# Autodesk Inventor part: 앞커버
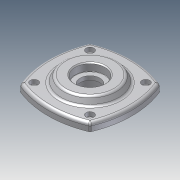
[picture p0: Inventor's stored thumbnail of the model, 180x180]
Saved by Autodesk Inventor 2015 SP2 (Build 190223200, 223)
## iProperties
Created: 2013-02
Part Number: 앞커버
Document SubType Name: Modeling
Designer: 한국산업디자인학원[gmhk.co.kr]
Density: 1 g/cm^3
Material: 일반
Appearance: 기본값
Mass: 76.2425 g
Surface Area: 198.108 cm^2
Volume: 76.2425 cm^3
Author: 한국산업디자인학원[gmhk.co.kr]
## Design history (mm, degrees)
sketch "스케치1"
  geometry: C1 r 30 at (0, 0) reference; A1 r 91.05 centre (0, -48.55) between (34.185, 35.839) and (-34.185, 35.839) reference; A2 r 91.05 centre (48.55, 0) between (-35.839, 34.185) and (-35.839, -34.185) reference; A3 r 3 centre (-33.058, 33.058) between (-34.185, 35.839) and (-35.839, 34.185) reference; A4 r 3 centre (33.058, 33.058) between (35.839, 34.185) and (34.185, 35.839) reference; A5 r 91.05 centre (-48.55, 0) between (35.839, -34.185) and (35.839, 34.185) reference; A6 r 3 centre (33.058, -33.058) between (34.185, -35.839) and (35.839, -34.185) reference; A7 r 91.05 centre (0, 48.55) between (-34.185, -35.839) and (34.185, -35.839) reference; A8 r 3 centre (-33.058, -33.058) between (-35.839, -34.185) and (-34.185, -35.839) reference; 1 further point
  node "참조1"
  node "참조2"
  node "참조3"
  node "참조4"
  node "참조5"
  node "참조6"
  node "참조7"
  node "참조8"
  node "참조9"
extrude "돌출1" new body sketch "스케치1" distance "d0" = 8; taper "d1" = 0 deg
sketch "스케치2"
  geometry: C1 r 30 at (0, 0); 1 further point
  constraints: 1 centre point, 1 coincident
  dimensions: "d2" = 60 diameter of C1
extrude "돌출2" join sketch "스케치2" distance "d3" = 7; taper "d4" = -30 deg
hole "구멍1" diameter "d7" = 20; stored, may be unused: countersink angle "d11" = 90 deg, drill point angle "d13" = 118 deg; dims "d5" = 10, "d6" = 10, "d8" = 6, "d9" = 30, "d10" = 8, "d12" = 20
sketch "스케치3"
  geometry: C1 r 1.621 at (28.284, 28.284) reference; C2 r 1.621 at (-28.284, 28.284) reference; C3 r 1.621 at (-28.284, -28.284) reference; C4 r 1.621 at (28.284, -28.284) reference; 1 further point
hole "구멍2" sketch "스케치3" at (28.284, 28.284), (28.284, -28.284), (-28.284, -28.284), (-28.284, 28.284) diameter "d14" = 4.5; stored, may be unused: countersink angle "d18" = 90 deg, drill point angle "d20" = 118 deg; dims "d15" = 6, "d16" = 8, "d17" = 4.4, "d19" = 20
extrude "돌출3" join sketch "스케치1" distance "d21" = 12; taper "d22" = 0 deg
hole "구멍3" diameter "d25" = 30; stored, may be unused: countersink angle "d29" = 90 deg, drill point angle "d31" = 0 deg; dims "d23" = 10, "d24" = 10, "d26" = 6, "d27" = 40, "d28" = 12, "d30" = 15
fillet "모깎기1" dims "d32" = 3, "d33" = 0.3
chamfer "모따기1" distance "d34" = 1; stored, may be unused: second distance "d35" = 2, angle "d36" = 45 deg
node "솔리드1"
node "참조10"
node "참조11"
node "참조12"
node "참조13"
